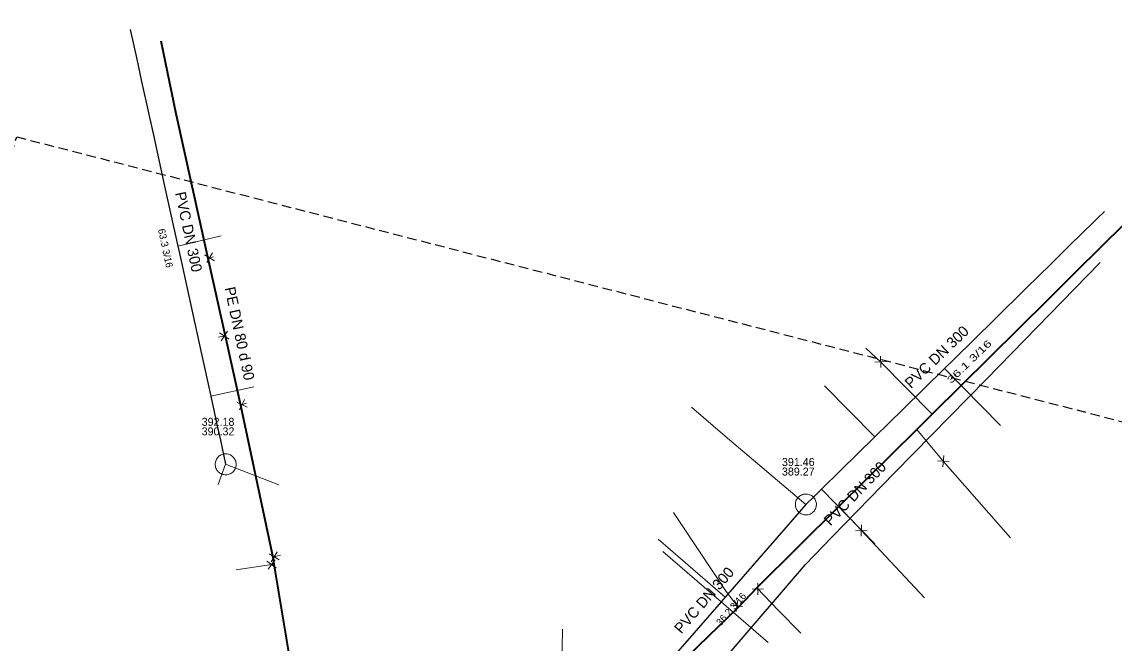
# Model space of a CAD drawing. Extents: x -772952 to -772403, y -1033777 to -1033210.
# Drawn here: x -772845.8 to -772723, y -1033306.9 to -1033237 of the extents above; entities that cross this region are included whole.
import ezdxf

# ---------------------------------------------------------------- set-up
doc = ezdxf.new("R2010")
doc.units = 0
doc.header["$LTSCALE"] = 0.36
doc.linetypes.add('MEDIUM_DASHED', pattern=[4.5, 3, -1.5])
for name, color, linetype, lineweight in [('15', 7, 'Continuous', 13), ('16', 7, 'Continuous', 35), ('2', 7, 'Continuous', 25), ('4', 7, 'Continuous', 13), ('57', 7, 'Continuous', 13), ('59', 7, 'Continuous', 13), ('62', 7, 'MEDIUM_DASHED', 25)]:
    doc.layers.add(name, color=color, linetype=linetype, lineweight=lineweight)
for name, color, linetype in [('17', 7, 'Continuous'), ('3', 7, 'Continuous'), ('6', 7, 'Continuous')]:
    doc.layers.add(name, color=color, linetype=linetype)

msp = doc.modelspace()

# ---------------------------------------------------------------- linework, layer by layer
at = {"layer": '15'}
for p, q in [((-772824.136, -1033263.884), (-772825.254, -1033263.218)), ((-772825.024, -1033264.104), (-772824.361, -1033262.997)), ((-772823.57, -1033271.992), (-772822.484, -1033272.709)), ((-772822.673, -1033271.813), (-772823.387, -1033272.888)), ((-772748.583, -1033275.245), (-772749.884, -1033275.292)), ((-772749.21, -1033275.912), (-772749.253, -1033274.622)), ((-772820.478, -1033280.387), (-772821.645, -1033279.809)), ((-772821.347, -1033280.675), (-772820.772, -1033279.52)), ((-772742.827, -1033286.396), (-772741.529, -1033286.484)), ((-772742.135, -1033285.797), (-772742.225, -1033287.085)), ((-772752.039, -1033294.227), (-772750.738, -1033294.272)), ((-772751.367, -1033293.606), (-772751.414, -1033294.896)), ((-772817.768, -1033297.764), (-772817.107, -1033296.655)), ((-772818.244, -1033297.681), (-772817.195, -1033298.451)), ((-772817.339, -1033297.547), (-772818.105, -1033298.586)), ((-772816.88, -1033297.542), (-772817.999, -1033296.878)), ((-772763.035, -1033300.185), (-772763.046, -1033301.475)), ((-772763.689, -1033300.824), (-772762.387, -1033300.833)), ((-772764.73, -1033302.81), (-772766.021, -1033302.644)), ((-772765.457, -1033303.366), (-772765.29, -1033302.086))]:
    msp.add_line(p, q, dxfattribs=at)
at = {"layer": '16'}
for points in [[(-772697.486, -1033237.004), (-772702.392, -1033240.537), (-772721.486, -1033259.44), (-772724.793, -1033262.712), (-772726.954, -1033264.853), (-772730.355, -1033268.219), (-772733.767, -1033271.598), (-772743.414, -1033281.146), (-772745.156, -1033282.871), (-772753.92, -1033291.547), (-772763.164, -1033300.699), (-772765.243, -1033302.896), (-772774.291, -1033311.64)], [(-772830.179, -1033239.149), (-772828.5, -1033247.329), (-772824.879, -1033263.6), (-772822.929, -1033272.329), (-772821.21, -1033280.149), (-772817.589, -1033297.25), (-772817.462, -1033298.026), (-772815.385, -1033310.626), (-772815.329, -1033310.96), (-772812.21, -1033310.989), (-772811.827, -1033311.001)]]:
    msp.add_lwpolyline(points, dxfattribs=at)
at = {"layer": '2'}
for points in [[(-772833.62, -1033237.88), (-772832.893, -1033241.192), (-772832.337, -1033243.724), (-772831.016, -1033249.75), (-772829.757, -1033255.491), (-772828.276, -1033262.239), (-772827.984, -1033263.574), (-772826.822, -1033268.872), (-772825.65, -1033274.215), (-772824.567, -1033279.149), (-772823.8, -1033282.647), (-772823.486, -1033284.081), (-772822.89, -1033286.8)], [(-772724.05, -1033258.34), (-772724.913, -1033259.187), (-772725.252, -1033259.521), (-772727.966, -1033262.186), (-772730.088, -1033264.27), (-772732.86, -1033266.993), (-772736.436, -1033270.505), (-772740.962, -1033274.95), (-772742.054, -1033276.023), (-772746.693, -1033280.578), (-772749.863, -1033283.692), (-772753.749, -1033287.508), (-772755.866, -1033289.587), (-772755.931, -1033289.648), (-772756.04, -1033289.758), (-772756.778, -1033290.483), (-772757.63, -1033291.32)], [(-772774.26, -1033317.38), (-772766.272, -1033308.08), (-772757.691, -1033298.091), (-772754.673, -1033294.967), (-772747.614, -1033287.734), (-772737.334, -1033277.2), (-772724.53, -1033264.08)], [(-772757.63, -1033291.32), (-772758.112, -1033291.874), (-772758.373, -1033292.175), (-772759.884, -1033293.912), (-772766.704, -1033301.754), (-772767.151, -1033302.269), (-772775.095, -1033311.403), (-772775.663, -1033312.056), (-772775.897, -1033312.326), (-772776.31, -1033312.8)]]:
    msp.add_lwpolyline(points, dxfattribs=at)
at = {"layer": '4'}
for points in [[(-772821.71, -1033286.8), (-772821.716, -1033286.681), (-772821.734, -1033286.564), (-772821.763, -1033286.448), (-772821.804, -1033286.337), (-772821.856, -1033286.23), (-772821.919, -1033286.129), (-772821.992, -1033286.034), (-772822.073, -1033285.948), (-772822.163, -1033285.87), (-772822.261, -1033285.801), (-772822.364, -1033285.743), (-772822.473, -1033285.696), (-772822.587, -1033285.659), (-772822.703, -1033285.634), (-772822.821, -1033285.622), (-772822.94, -1033285.621), (-772823.059, -1033285.632), (-772823.175, -1033285.655), (-772823.289, -1033285.689), (-772823.399, -1033285.735), (-772823.504, -1033285.792), (-772823.602, -1033285.859), (-772823.693, -1033285.935), (-772823.776, -1033286.02), (-772823.85, -1033286.114), (-772823.914, -1033286.214), (-772823.968, -1033286.32), (-772824.011, -1033286.431), (-772824.043, -1033286.545), (-772824.062, -1033286.663), (-772824.07, -1033286.782), (-772824.066, -1033286.9), (-772824.05, -1033287.018), (-772824.022, -1033287.134), (-772823.983, -1033287.246), (-772823.932, -1033287.354), (-772823.871, -1033287.456), (-772823.8, -1033287.552), (-772823.72, -1033287.639), (-772823.631, -1033287.719), (-772823.535, -1033287.789), (-772823.432, -1033287.849), (-772823.324, -1033287.898), (-772823.211, -1033287.936), (-772823.095, -1033287.962), (-772822.977, -1033287.977), (-772822.858, -1033287.98), (-772822.74, -1033287.971), (-772822.622, -1033287.95), (-772822.508, -1033287.917), (-772822.398, -1033287.873), (-772822.292, -1033287.818), (-772822.193, -1033287.752), (-772822.1, -1033287.677), (-772822.016, -1033287.593), (-772821.941, -1033287.501), (-772821.875, -1033287.402), (-772821.819, -1033287.297), (-772821.775, -1033287.187), (-772821.741, -1033287.073), (-772821.72, -1033286.956), (-772821.71, -1033286.837)], [(-772756.45, -1033291.32), (-772756.456, -1033291.201), (-772756.474, -1033291.084), (-772756.503, -1033290.968), (-772756.544, -1033290.857), (-772756.596, -1033290.75), (-772756.659, -1033290.649), (-772756.732, -1033290.554), (-772756.813, -1033290.468), (-772756.903, -1033290.39), (-772757.001, -1033290.321), (-772757.104, -1033290.263), (-772757.213, -1033290.216), (-772757.327, -1033290.179), (-772757.443, -1033290.154), (-772757.561, -1033290.142), (-772757.68, -1033290.141), (-772757.799, -1033290.152), (-772757.915, -1033290.175), (-772758.029, -1033290.209), (-772758.139, -1033290.255), (-772758.244, -1033290.312), (-772758.342, -1033290.379), (-772758.433, -1033290.455), (-772758.516, -1033290.54), (-772758.59, -1033290.634), (-772758.654, -1033290.734), (-772758.708, -1033290.84), (-772758.751, -1033290.951), (-772758.783, -1033291.065), (-772758.802, -1033291.183), (-772758.81, -1033291.302), (-772758.806, -1033291.42), (-772758.79, -1033291.538), (-772758.762, -1033291.654), (-772758.723, -1033291.766), (-772758.672, -1033291.874), (-772758.611, -1033291.976), (-772758.54, -1033292.072), (-772758.46, -1033292.159), (-772758.371, -1033292.239), (-772758.275, -1033292.309), (-772758.172, -1033292.369), (-772758.064, -1033292.418), (-772757.951, -1033292.456), (-772757.835, -1033292.482), (-772757.717, -1033292.497), (-772757.598, -1033292.5), (-772757.48, -1033292.491), (-772757.362, -1033292.47), (-772757.248, -1033292.437), (-772757.138, -1033292.393), (-772757.032, -1033292.338), (-772756.933, -1033292.272), (-772756.84, -1033292.197), (-772756.756, -1033292.113), (-772756.681, -1033292.021), (-772756.615, -1033291.922), (-772756.559, -1033291.817), (-772756.515, -1033291.707), (-772756.481, -1033291.593), (-772756.46, -1033291.476), (-772756.45, -1033291.357)]]:
    msp.add_lwpolyline(points, close=True, dxfattribs=at)
at = {"layer": '57'}
for p, q in [((-772828.276, -1033262.239), (-772823.38, -1033261.1)), ((-772742.054, -1033276.023), (-772735.74, -1033282.45)), ((-772824.567, -1033279.149), (-772819.74, -1033278.08)), ((-772749.863, -1033283.692), (-772755.52, -1033277.96)), ((-772822.89, -1033286.8), (-772823.75, -1033289.079)), ((-772822.89, -1033286.8), (-772816.926, -1033289.098)), ((-772755.866, -1033289.587), (-772749.86, -1033295.75)), ((-772767.151, -1033302.269), (-772773.71, -1033296.62)), ((-772767.151, -1033302.269), (-772761.87, -1033306.86))]:
    msp.add_line(p, q, dxfattribs=at)
for points in [[(-772757.63, -1033291.32), (-772766.707, -1033283.647), (-772770.51, -1033280.36)], [(-772766.704, -1033301.754), (-772771.473, -1033297.618), (-772774.25, -1033295.21)]]:
    msp.add_lwpolyline(points, dxfattribs=at)
at = {"layer": '59'}
for p, q in [((-772824.879, -1033263.6), (-772824.25, -1033263.44)), ((-772822.929, -1033272.329), (-772823.71, -1033272.489)), ((-772821.21, -1033280.149), (-772820.559, -1033279.929)), ((-772817.589, -1033297.25), (-772816.73, -1033297.03)), ((-772817.462, -1033298.026), (-772821.699, -1033298.679))]:
    msp.add_line(p, q, dxfattribs=at)
for points in [[(-772743.414, -1033281.146), (-772749.233, -1033275.269), (-772750.888, -1033273.728)], [(-772745.156, -1033282.871), (-772742.18, -1033286.44), (-772734.62, -1033295.09)], [(-772753.92, -1033291.547), (-772751.39, -1033294.25), (-772744.31, -1033301.82)], [(-772765.244, -1033302.897), (-772765.375, -1033302.728), (-772766.609, -1033301.129), (-772772.535, -1033292.214)], [(-772763.164, -1033300.699), (-772760.73, -1033303.25), (-772758.199, -1033305.809)], [(-772785.148, -1033311.823), (-772785.145, -1033311.709), (-772785.05, -1033307.469), (-772784.989, -1033305.37)]]:
    msp.add_lwpolyline(points, dxfattribs=at)
at = {"layer": '62'}
msp.add_lwpolyline([(-772641.514, -1033776.98), (-772641.529, -1033776.987), (-772951.708, -1033584.106), (-772846.395, -1033249.938), (-772562.451, -1033323.146)], close=True, dxfattribs=at)

# ---------------------------------------------------------------- texts
at = {"layer": '17'}
msp.add_text('PE DN 80 d 90 ', height=1.2, rotation=282, dxfattribs=at).set_placement((-772823.022, -1033266.967))
at = {"layer": '3'}
for s, height, rotation, p in [('PVC DN 300', 1.2, 282, (-772828.59, -1033256.268)), ('63.3 3/16', 0.8, 282, (-772830.504, -1033260.375)), ('PVC DN 300', 1.2, 44, (-772745.802, -1033278.34)), ('PVC DN 300', 1.2, 46, (-772754.871, -1033293.804)), ('PVC DN 300', 1.2, 49, (-772771.64, -1033305.949)), ('36.2 3/16', 0.8, 49, (-772767.202, -1033305.037))]:
    msp.add_text(s, height=height, rotation=rotation, dxfattribs=at).set_placement(p)
at = {"layer": '3', "width": 1.45}
msp.add_text('36.1 3/16', height=0.8, rotation=44, dxfattribs=at).set_placement((-772741.307, -1033277.777))
at = {"layer": '6'}
for s, p in [('392.18', (-772825.588, -1033282.467)), ('390.32', (-772825.588, -1033283.544)), ('391.46', (-772760.328, -1033286.987)), ('389.27', (-772760.328, -1033288.064))]:
    msp.add_text(s, height=0.9, dxfattribs=at).set_placement(p)

doc.saveas('drawing.dxf')
